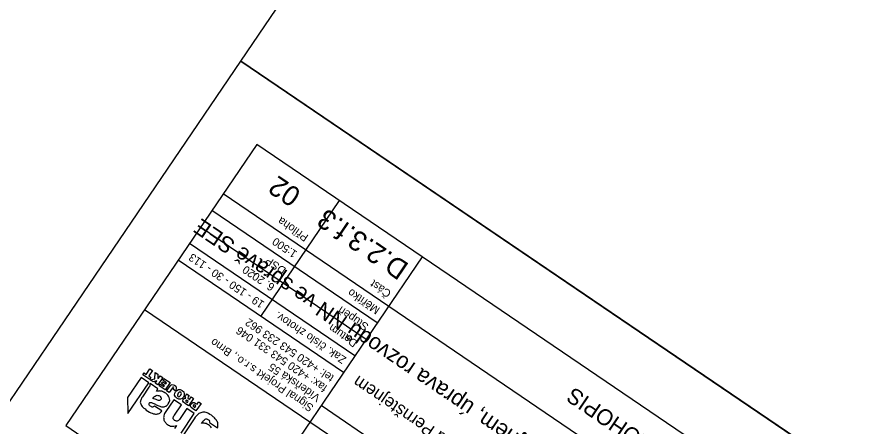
# Model space of a CAD drawing. Extents: x -621145 to -620023, y -1122866 to -1121971.
# Drawn here: x -621089.5 to -620982.6, y -1122139.7 to -1122088.4 of the extents above; entities that cross this region are included whole.
import ezdxf

# ---------------------------------------------------------------- set-up
doc = ezdxf.new("R2010")
doc.units = 0
for name, color, linetype in [('Info o rozpiskách', 7, 'Continuous'), ('popis', 7, 'Continuous'), ('Ramečky', 7, 'Continuous'), ('RÁMY', 7, 'Continuous'), ('Text', 7, 'Continuous'), ('Text barevný', 7, 'Continuous')]:
    doc.layers.add(name, color=color, linetype=linetype)

msp = doc.modelspace()

# ---------------------------------------------------------------- linework, layer by layer
at = {"layer": 'Info o rozpiskách'}
for points in [[(-621072.95, -1122133.72), (-621073.8, -1122133.15), (-621073.64, -1122132.91), (-621073.37, -1122133.09), (-621072.91, -1122132.41), (-621072.61, -1122132.62), (-621073.07, -1122133.29), (-621072.79, -1122133.48), (-621072.95, -1122133.72)], [(-621071.94, -1122134.41), (-621072.25, -1122134.2), (-621072.05, -1122133.91), (-621072.51, -1122134.02), (-621072.87, -1122133.78), (-621072.29, -1122133.66), (-621072.28, -1122132.84), (-621071.92, -1122133.08), (-621071.94, -1122133.6), (-621071.83, -1122133.57), (-621071.63, -1122133.28), (-621071.32, -1122133.49), (-621071.94, -1122134.41)], [(-621071.02, -1122135.03), (-621071.77, -1122134.52), (-621071.63, -1122134.32), (-621071.18, -1122134.62), (-621071.09, -1122134.48), (-621071.47, -1122134.22), (-621071.32, -1122134.01), (-621070.94, -1122134.26), (-621070.85, -1122134.13), (-621071.32, -1122133.81), (-621071.17, -1122133.59), (-621070.4, -1122134.11), (-621071.02, -1122135.03)], [(-621070.53, -1122135.37), (-621070.83, -1122135.16), (-621070.44, -1122134.59), (-621070.29, -1122134.44), (-621070.12, -1122134.37), (-621069.84, -1122134.46), (-621069.69, -1122134.58), (-621069.62, -1122134.72), (-621069.62, -1122134.89), (-621069.7, -1122135.07), (-621069.75, -1122135.14), (-621070.02, -1122134.96), (-621069.93, -1122134.79), (-621069.96, -1122134.7), (-621070.04, -1122134.7), (-621070.11, -1122134.76), (-621070.53, -1122135.37)], [(-621069.55, -1122136.07), (-621069.74, -1122135.89), (-621069.83, -1122135.68), (-621069.81, -1122135.46), (-621069.72, -1122135.27), (-621069.55, -1122135.09), (-621069.36, -1122135), (-621069.13, -1122135), (-621068.89, -1122135.1), (-621068.7, -1122135.29), (-621068.62, -1122135.51), (-621068.65, -1122135.72), (-621068.74, -1122135.93), (-621068.9, -1122136.09), (-621069.09, -1122136.17), (-621069.32, -1122136.18), (-621069.55, -1122136.07)], [(-621069.4, -1122135.84), (-621069.31, -1122135.88), (-621069.22, -1122135.87), (-621069.05, -1122135.71), (-621068.96, -1122135.48), (-621069.05, -1122135.33), (-621069.25, -1122135.3), (-621069.4, -1122135.45), (-621069.48, -1122135.67), (-621069.47, -1122135.77), (-621069.4, -1122135.84)], [(-621068.08, -1122137.03), (-621068.53, -1122136.73), (-621068.72, -1122136.57), (-621068.81, -1122136.42), (-621068.75, -1122136.19), (-621068.61, -1122136.07), (-621068.45, -1122136.07), (-621068.52, -1122135.89), (-621068.43, -1122135.72), (-621068.39, -1122135.65), (-621068.35, -1122135.58), (-621068.35, -1122135.54), (-621068.34, -1122135.51), (-621068.03, -1122135.72), (-621068.12, -1122135.9), (-621068.17, -1122136.08), (-621068.11, -1122136.13), (-621068.03, -1122136.2), (-621067.98, -1122136.23), (-621067.76, -1122135.91), (-621067.46, -1122136.11), (-621068.08, -1122137.03)], [(-621068.24, -1122136.62), (-621068.12, -1122136.43), (-621068.25, -1122136.34), (-621068.38, -1122136.3), (-621068.44, -1122136.34), (-621068.45, -1122136.43), (-621068.39, -1122136.52), (-621068.24, -1122136.62)], [(-621067.16, -1122137.66), (-621067.6, -1122137.36), (-621067.76, -1122137.23), (-621067.84, -1122137.08), (-621067.85, -1122136.93), (-621067.77, -1122136.77), (-621067.55, -1122136.6), (-621067.38, -1122136.62), (-621067.18, -1122136.72), (-621067.03, -1122136.82), (-621066.83, -1122136.54), (-621066.53, -1122136.74), (-621067.16, -1122137.66)], [(-621067.32, -1122137.25), (-621067.17, -1122137.04), (-621067.31, -1122136.95), (-621067.4, -1122136.92), (-621067.5, -1122136.98), (-621067.51, -1122137.07), (-621067.4, -1122137.19), (-621067.32, -1122137.25)]]:
    msp.add_lwpolyline(points, dxfattribs=at)
at = {"layer": 'popis'}
for points in [[(-621075.66, -1122137.97), (-621073.05, -1122134.14), (-621074.01, -1122133.49), (-621075.7, -1122135.98), (-621075.66, -1122137.97)], [(-621071.44, -1122137.67), (-621072.36, -1122137.05), (-621072.41, -1122137.11), (-621072.46, -1122137.15), (-621072.52, -1122137.17), (-621072.58, -1122137.18), (-621072.65, -1122137.18), (-621072.72, -1122137.15), (-621072.77, -1122137.11), (-621072.84, -1122137.07), (-621072.91, -1122137.02), (-621072.97, -1122136.97), (-621073, -1122136.9), (-621073.02, -1122136.87), (-621073.03, -1122136.81), (-621073.04, -1122136.76), (-621073.02, -1122136.72), (-621073.01, -1122136.67), (-621072.96, -1122136.65), (-621072.93, -1122136.6), (-621072.87, -1122136.6), (-621072.81, -1122136.6), (-621072.73, -1122136.6), (-621072.64, -1122136.64), (-621072.55, -1122136.68), (-621072.45, -1122136.72), (-621072.35, -1122136.78), (-621072.24, -1122136.83), (-621072.14, -1122136.88), (-621072.03, -1122136.93), (-621071.91, -1122136.98), (-621071.8, -1122137.03), (-621071.7, -1122137.06), (-621071.59, -1122137.1), (-621071.48, -1122137.13), (-621071.35, -1122137.14), (-621071.23, -1122137.13), (-621071.14, -1122137.14), (-621071.04, -1122137.12), (-621070.96, -1122137.08), (-621070.9, -1122137.06), (-621070.83, -1122137.01), (-621070.78, -1122136.96), (-621070.71, -1122136.9), (-621070.66, -1122136.84), (-621070.62, -1122136.77), (-621070.5, -1122136.56), (-621070.45, -1122136.35), (-621070.46, -1122136.15), (-621070.51, -1122135.99), (-621070.59, -1122135.82), (-621070.7, -1122135.67), (-621070.81, -1122135.55), (-621070.94, -1122135.45), (-621071.01, -1122135.41), (-621071.06, -1122135.38), (-621071.13, -1122135.33), (-621071.21, -1122135.3), (-621071.26, -1122135.28), (-621071.33, -1122135.24), (-621071.4, -1122135.21), (-621071.47, -1122135.19), (-621071.54, -1122135.19), (-621071.62, -1122135.18), (-621071.69, -1122135.17), (-621071.78, -1122135.16), (-621071.85, -1122135.17), (-621071.93, -1122135.19), (-621072.02, -1122135.19), (-621072.09, -1122135.2), (-621071.91, -1122134.9), (-621072.9, -1122134.23), (-621072.93, -1122134.27), (-621072.91, -1122134.36), (-621072.91, -1122134.41), (-621072.92, -1122134.47), (-621072.94, -1122134.5), (-621072.95, -1122134.56), (-621072.97, -1122134.59), (-621073.01, -1122134.63), (-621073.05, -1122134.69), (-621073.86, -1122135.88), (-621073.92, -1122135.98), (-621073.97, -1122136.1), (-621074.02, -1122136.2), (-621074.06, -1122136.31), (-621074.09, -1122136.4), (-621074.11, -1122136.48), (-621074.12, -1122136.57), (-621074.1, -1122136.69), (-621074.06, -1122136.79), (-621074.03, -1122136.88), (-621073.97, -1122136.99), (-621073.89, -1122137.1), (-621073.8, -1122137.19), (-621073.67, -1122137.3), (-621073.53, -1122137.42), (-621073.38, -1122137.56), (-621073.18, -1122137.68), (-621072.97, -1122137.8), (-621072.81, -1122137.88), (-621072.65, -1122137.96), (-621072.49, -1122138.01), (-621072.36, -1122138.04), (-621072.23, -1122138.05), (-621072.1, -1122138.05), (-621071.99, -1122138.04), (-621071.89, -1122138.02), (-621071.78, -1122137.99), (-621071.7, -1122137.93), (-621071.64, -1122137.88), (-621071.56, -1122137.82), (-621071.5, -1122137.76), (-621071.44, -1122137.67)], [(-621072.55, -1122136.1), (-621072.54, -1122136.09), (-621072.52, -1122136.06), (-621072.51, -1122136.05), (-621072.43, -1122135.95), (-621072.34, -1122135.85), (-621072.25, -1122135.8), (-621072.14, -1122135.74), (-621072.03, -1122135.71), (-621071.93, -1122135.72), (-621071.82, -1122135.74), (-621071.72, -1122135.78), (-621071.65, -1122135.82), (-621071.61, -1122135.87), (-621071.58, -1122135.93), (-621071.55, -1122135.98), (-621071.53, -1122136.04), (-621071.52, -1122136.11), (-621071.51, -1122136.17), (-621071.55, -1122136.23), (-621071.63, -1122136.32), (-621071.74, -1122136.36), (-621071.86, -1122136.35), (-621071.98, -1122136.31), (-621072.13, -1122136.25), (-621072.26, -1122136.19), (-621072.41, -1122136.14), (-621072.55, -1122136.1)], [(-621069.03, -1122140.43), (-621067.37, -1122137.99), (-621068.3, -1122137.37), (-621069.14, -1122138.61), (-621069.23, -1122138.74), (-621069.34, -1122138.85), (-621069.43, -1122138.89), (-621069.5, -1122138.93), (-621069.58, -1122138.93), (-621069.66, -1122138.92), (-621069.74, -1122138.88), (-621069.83, -1122138.84), (-621069.9, -1122138.77), (-621069.94, -1122138.72), (-621070, -1122138.65), (-621070, -1122138.58), (-621070, -1122138.5), (-621069.98, -1122138.41), (-621069.92, -1122138.29), (-621069.85, -1122138.19), (-621068.98, -1122136.9), (-621069.92, -1122136.27), (-621070.92, -1122137.73), (-621071.01, -1122137.86), (-621071.08, -1122137.99), (-621071.14, -1122138.12), (-621071.17, -1122138.26), (-621071.2, -1122138.38), (-621071.21, -1122138.49), (-621071.19, -1122138.61), (-621071.19, -1122138.71), (-621071.16, -1122138.81), (-621071.13, -1122138.91), (-621071.07, -1122138.98), (-621071.02, -1122139.07), (-621070.94, -1122139.17), (-621070.88, -1122139.24), (-621070.81, -1122139.3), (-621070.72, -1122139.37), (-621070.6, -1122139.44), (-621070.47, -1122139.49), (-621070.36, -1122139.55), (-621070.21, -1122139.56), (-621070.07, -1122139.58), (-621069.92, -1122139.57), (-621069.77, -1122139.53), (-621069.59, -1122139.49), (-621069.85, -1122139.87)], [(-621065.24, -1122139.76), (-621065.31, -1122139.66), (-621065.4, -1122139.56), (-621065.49, -1122139.48), (-621065.59, -1122139.41), (-621065.69, -1122139.34), (-621065.78, -1122139.3), (-621065.9, -1122139.24), (-621066.02, -1122139.22), (-621066.13, -1122139.2), (-621066.25, -1122139.2), (-621066.35, -1122139.21), (-621066.47, -1122139.24), (-621066.32, -1122139.02), (-621066.21, -1122138.85), (-621066.11, -1122138.77), (-621066.01, -1122138.71), (-621065.94, -1122138.67), (-621065.85, -1122138.66), (-621065.78, -1122138.68), (-621065.69, -1122138.71), (-621065.62, -1122138.76), (-621065.58, -1122138.79), (-621065.53, -1122138.83), (-621065.49, -1122138.88), (-621065.47, -1122138.92), (-621065.46, -1122138.97), (-621065.45, -1122139.02), (-621065.46, -1122139.06), (-621065.47, -1122139.11), (-621064.49, -1122139.77), (-621064.43, -1122139.63), (-621064.42, -1122139.52), (-621064.41, -1122139.39), (-621064.42, -1122139.28), (-621064.43, -1122139.15), (-621064.49, -1122139.04), (-621064.55, -1122138.95), (-621064.61, -1122138.82), (-621064.68, -1122138.72), (-621064.76, -1122138.63), (-621064.84, -1122138.54), (-621064.93, -1122138.45), (-621065.01, -1122138.38), (-621065.08, -1122138.32), (-621065.17, -1122138.25), (-621065.24, -1122138.2), (-621065.41, -1122138.1), (-621065.59, -1122138), (-621065.76, -1122137.92), (-621065.9, -1122137.87), (-621066.05, -1122137.82), (-621066.2, -1122137.8), (-621066.32, -1122137.81), (-621066.44, -1122137.84), (-621066.57, -1122137.88), (-621066.69, -1122137.93), (-621066.8, -1122138), (-621066.92, -1122138.09), (-621067.02, -1122138.2), (-621067.15, -1122138.32), (-621067.25, -1122138.46), (-621067.37, -1122138.63), (-621068.73, -1122140.64)]]:
    msp.add_lwpolyline(points, dxfattribs=at)
at = {"layer": 'Ramečky'}
for p, q in [((-621059.57, -1122104.34), (-621083.44, -1122139.49)), ((-620985.11, -1122154.9), (-621059.57, -1122104.34)), ((-620989.33, -1122161.1), (-621063.78, -1122110.54)), ((-621044.5, -1122126.65), (-621065.19, -1122112.61)), ((-621045.91, -1122128.72), (-621066.59, -1122114.68)), ((-621047.31, -1122130.79), (-621067.99, -1122116.75)), ((-621038.89, -1122118.38), (-621062.76, -1122153.54)), ((-621048.72, -1122132.86), (-621069.4, -1122118.81)), ((-620997.76, -1122173.51), (-621051.53, -1122137)), ((-621083.44, -1122139.49), (-621008.99, -1122190.06)), ((-620999.16, -1122175.58), (-621052.93, -1122139.06))]:
    msp.add_line(p, q, dxfattribs=at)
for points in [[(-621059.06, -1122125.84), (-621049.23, -1122111.36)], [(-621052.93, -1122139.06), (-621073.61, -1122125.02)]]:
    msp.add_lwpolyline(points, dxfattribs=at)
at = {"layer": 'RÁMY'}
for points in [[(-620978.13, -1121971.07), (-620891.27, -1122030.06), (-620974.7, -1122152.91), (-621061.56, -1122093.92)], [(-621061.56, -1122093.92), (-620106.07, -1122742.82), (-620189.51, -1122865.67), (-621144.99, -1122216.77)]]:
    msp.add_lwpolyline(points, close=True, dxfattribs=at)

# ---------------------------------------------------------------- texts
at = {"layer": 'Text'}
for s, p in [('Příloha', (-621053.02, -1122115.74)), ('1:500', (-621054.42, -1122117.8)), ('19 - 150 - 30 - 113', (-621058.52, -1122124.09)), ('DSP', (-621055.82, -1122119.87)), ('6. 2020', (-621057.23, -1122121.94)), ('Část', (-621042.67, -1122122.76)), ('Měřítko', (-621044.08, -1122124.83)), ('Stupeň', (-621045.48, -1122126.9)), ('Zak. číslo zhotov.', (-621048.29, -1122131.03)), ('tel: +420 543 233 962', (-621049.83, -1122133.31)), ('Datum', (-621046.89, -1122128.96)), ('fax: +420 543 331 046', (-621050.67, -1122134.55)), ('Signal Projekt s.r.o., Brno', (-621052.37, -1122137.03)), ('Vídeňská 55', (-621051.52, -1122135.79))]:
    msp.add_text(s, height=1, rotation=145.8181, dxfattribs=at).set_placement(p)
at = {"layer": 'Text barevný'}
for s, height, p in [('02', 2.5, (-621053.86, -1122110.23)), ('D.2.3.f.3', 2.5, (-621040.41, -1122119.36)), ('SO 06-06-04 Bystřice nad Pernštějnem, úprava rozvodů NN ve správě SEE', 2, (-620992.49, -1122163.79)), ('Oprava zabezpečovacího zařízení v ŽST Bystřice nad Pernštejnem', 1.5589, (-620995.49, -1122168.05)), ('POLOHOPIS', 2, (-621006.9, -1122143.46))]:
    msp.add_text(s, height=height, rotation=145.8181, dxfattribs=at).set_placement(p)

doc.saveas('drawing.dxf')
